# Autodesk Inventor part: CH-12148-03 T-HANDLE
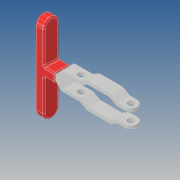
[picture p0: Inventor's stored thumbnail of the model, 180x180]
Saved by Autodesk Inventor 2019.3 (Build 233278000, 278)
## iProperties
Created: 2017-11
Part Number: CH-12148-03 T-HANDLE
Material: Ogólny
Document SubType Name: Modeling
Designer: Admin
Density: 1 g/cm^3
Appearance: Domyślna
Author: Admin
Revision Number: ÈÎºÎ
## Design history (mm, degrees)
feature "Ô²½Ç3"
node "Bryła1"
